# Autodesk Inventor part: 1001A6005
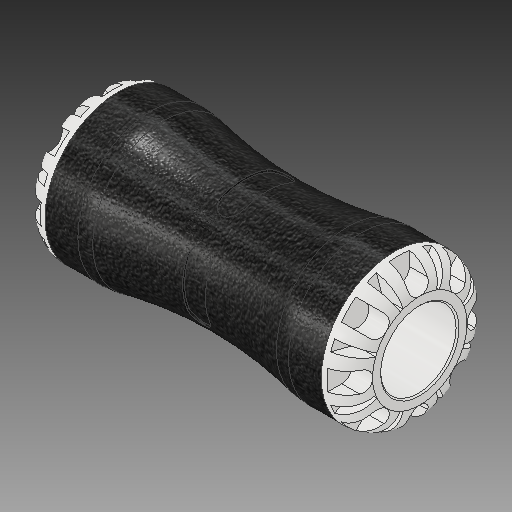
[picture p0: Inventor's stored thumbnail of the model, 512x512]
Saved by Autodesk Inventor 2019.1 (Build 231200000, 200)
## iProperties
Created: 2016-12
Part Number: 1001A6005
Material: PVC-Piping
Description: PLASSON COUPLER 1/2''IPS x 1/2''IPS SERIES 1
Document SubType Name: Modeling
Designer: KIM
Mass: 95.2094 g
Surface Area: 200.83 cm^2
Volume: 68.0067 cm^3
Density: 1.4 g/cm^3
Appearance: White
ILogicFactory: False
Author: KIM
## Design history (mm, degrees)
derived "1001A.ipt"
feature "Solid1::1001A.ipt"
tag "TaggingFeature1"
body "Solid1"
other parameters: "d2" = 44.958, "d4" = 1.76667, "d11" = 5.7576, "d13" = 5.7576, "d14" = 0, "d16" = 360 deg, "d18" = 8 deg, "d19" = 0.424, "d20" = 8 deg, "d21" = 0.424, "d23" = 0, "d25" = 360 deg, "d27" = 16.3576, "d28" = 6.36, "d29" = 6.36, "d30" = 6.36, "d31" = 0, "d33" = 0, "d37" = 18.3896, "d38" = 0.40894, "d43" = 2.65, "d44" = 21.2, "d45" = 18.3896, "d46" = 34.7599, "d47" = 40.894, "d48" = 91.948, "d50" = 360 deg, "d54" = 0.513, "d_" = 21.2, "E_" = 40.894, "H_" = 91.948, "l_" = 44.958, "d12" = 26.5, "d42" = 40.894, "d52" = 7.197
